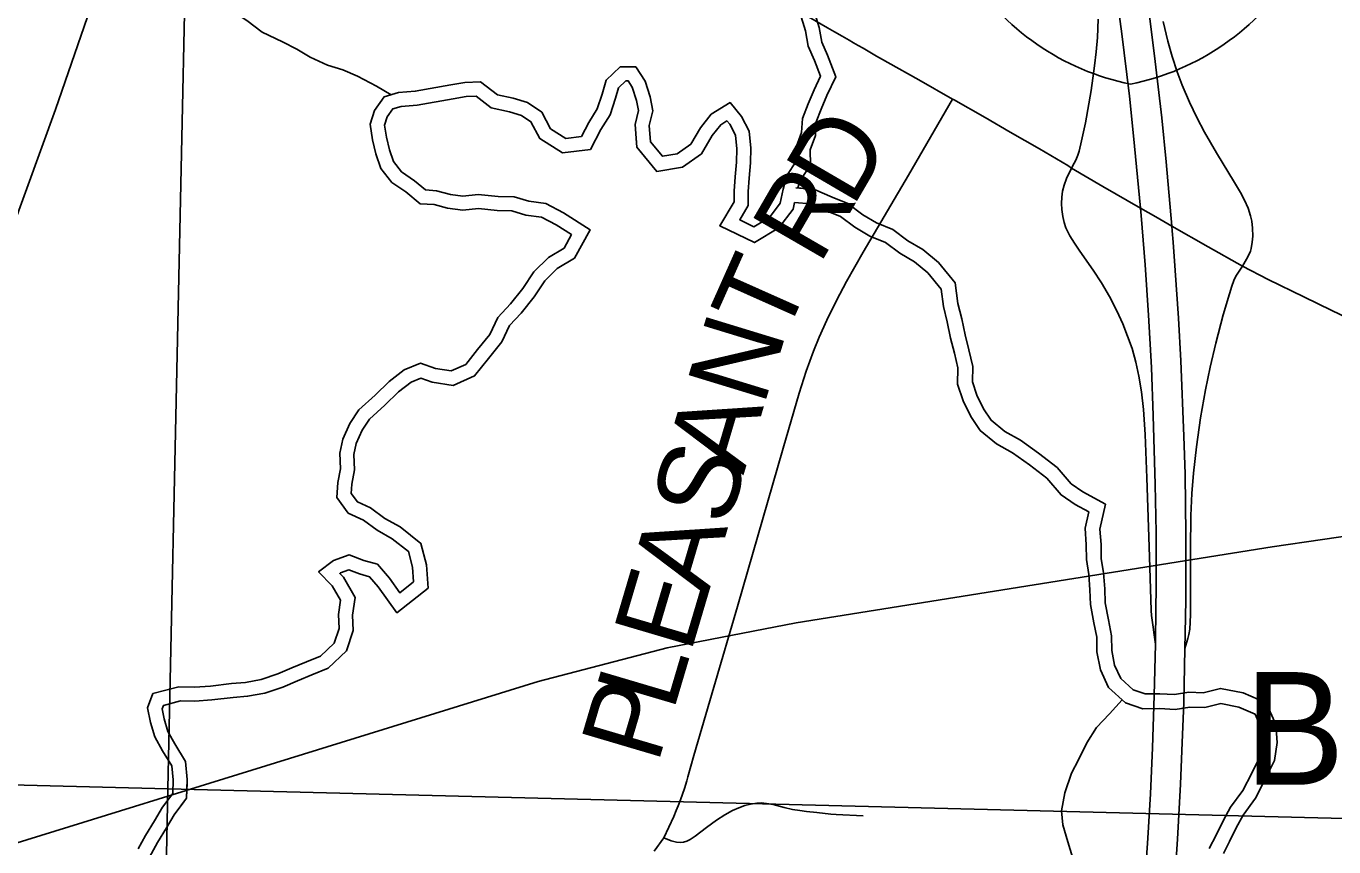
# Model space of a CAD drawing. Extents: x 0 to 34, y 0 to 22.
# Drawn here: x 29.042 to 29.958, y 19.567 to 20.143 of the extents above; entities that cross this region are included whole.
import ezdxf

# ---------------------------------------------------------------- set-up
doc = ezdxf.new("R2010")
doc.units = 0
for name, color, linetype in [('GM_X_Corporation', 7, 'Continuous'), ('GM_X_County_Road', 7, 'Continuous'), ('GM_X_County_Road_Text', 7, 'Continuous'), ('GM_X_Interchange_Ramps', 7, 'Continuous'), ('GM_X_Interstate_Route', 7, 'Continuous'), ('GM_X_Interstate_Shield', 7, 'Continuous'), ('GM_X_Major_River', 7, 'Continuous'), ('GM_X_Minor_River', 7, 'Continuous'), ('GM_X_Rail_Line', 7, 'Continuous'), ('GM_X_State_Route', 7, 'Continuous'), ('GM_X_Township_Road', 7, 'Continuous'), ('GM_X_Unincorporated_Text', 7, 'Continuous')]:
    doc.layers.add(name, color=color, linetype=linetype)

msp = doc.modelspace()

# ---------------------------------------------------------------- linework, layer by layer
at = {"layer": 'GM_X_Corporation'}
for points in [[(28.15826, 20.64503), (29.16312, 20.61871), (29.14139, 19.60821), (28.13428, 19.63375)], [(29.16312, 20.61871), (29.66671, 20.60283), (30.17754, 20.58732), (30.18242, 20.58723), (30.15988, 19.58241), (29.14139, 19.60821)], [(30.15988, 19.58241), (30.13818, 18.56889), (29.12079, 18.59588), (29.14139, 19.60821)]]:
    msp.add_lwpolyline(points, close=True, dxfattribs=at)
at = {"layer": 'GM_X_County_Road'}
for points in [[(29.5056, 19.61665), (29.50985, 19.63157), (29.52386, 19.67928), (29.54025, 19.73585), (29.57229, 19.84674), (29.58363, 19.88549), (29.58855, 19.90085), (29.59364, 19.91483), (29.59758, 19.9246), (29.60286, 19.93649), (29.6097, 19.95041), (29.61667, 19.96357), (29.62828, 19.9841), (29.66011, 20.0382), (29.68838, 20.0869), (29.69105, 20.09149)], [(29.48863, 19.57377), (29.49573, 19.58872), (29.49749, 19.59284), (29.49877, 19.59613), (29.50038, 19.60046), (29.50315, 19.6084), (29.50481, 19.61385), (29.5056, 19.61665)], [(29.48199, 19.56437), (29.48863, 19.57377)]]:
    msp.add_lwpolyline(points, dxfattribs=at)
at = {"layer": 'GM_X_Interchange_Ramps'}
for points in [[(29.79303, 20.14754), (29.79241, 20.13451), (29.79162, 20.12461), (29.79052, 20.11475), (29.78807, 20.09755), (29.78406, 20.07493), (29.78143, 20.06217), (29.77964, 20.05495), (29.77879, 20.05221), (29.7773, 20.04877), (29.77609, 20.04647), (29.77427, 20.04315)], [(29.8942, 19.97448), (29.89792, 19.98093), (29.89965, 19.98491), (29.9002, 19.98683), (29.90094, 19.99111), (29.90127, 19.99544), (29.90116, 20.00104), (29.90056, 20.00596), (29.89981, 20.0096), (29.89814, 20.01494), (29.89559, 20.02059), (29.8927, 20.02607), (29.88858, 20.03302), (29.87598, 20.05371), (29.86756, 20.06821), (29.86206, 20.07864), (29.857, 20.08929), (29.85192, 20.10131), (29.84843, 20.11061), (29.84493, 20.12122), (29.84184, 20.13196), (29.83854, 20.14585)], [(29.77427, 20.04315), (29.77089, 20.03589), (29.76917, 20.03122), (29.76806, 20.02701), (29.76743, 20.02271), (29.76724, 20.01837), (29.76747, 20.01402), (29.76816, 20.00909), (29.76924, 20.00489), (29.77043, 20.00135), (29.7731, 19.99574), (29.77635, 19.99045), (29.78019, 19.9848), (29.78944, 19.97153), (29.79522, 19.96268), (29.80089, 19.95303), (29.80602, 19.94309), (29.81017, 19.93405), (29.81365, 19.9254), (29.81672, 19.91658), (29.81939, 19.907), (29.82156, 19.8973), (29.8234, 19.88626), (29.82473, 19.8739), (29.82583, 19.85652), (29.82707, 19.82608), (29.82891, 19.77077), (29.83002, 19.73301), (29.83042, 19.72952), (29.83073, 19.72636), (29.83145, 19.72133), (29.83221, 19.71605), (29.83313, 19.70959)], [(29.85379, 19.70653), (29.8557, 19.71347), (29.85651, 19.71639), (29.85711, 19.72012), (29.85764, 19.73001), (29.85773, 19.74739), (29.85769, 19.77596), (29.85797, 19.79955), (29.8587, 19.81505), (29.85983, 19.82929), (29.86188, 19.8478), (29.86478, 19.86809), (29.86809, 19.88768), (29.87134, 19.90349), (29.87534, 19.92041), (29.88051, 19.94022), (29.88491, 19.9551), (29.88664, 19.96036), (29.88794, 19.96429), (29.88871, 19.96596), (29.88994, 19.96802), (29.8942, 19.97448)]]:
    msp.add_lwpolyline(points, dxfattribs=at)
at = {"layer": 'GM_X_Interstate_Route'}
for points in [[(29.84542, 19.99124), (29.84478, 19.9992), (29.84449, 20.00246), (29.84059, 20.04748), (29.83748, 20.07838), (29.83297, 20.11788), (29.82873, 20.15177), (29.82454, 20.18192), (29.81814, 20.22429), (29.81289, 20.25616), (29.80444, 20.30387), (29.80109, 20.3216), (29.7974, 20.3411), (29.79259, 20.36484), (29.78366, 20.40612), (29.77461, 20.44548), (29.76021, 20.50592), (29.75342, 20.53433), (29.74589, 20.56638), (29.72925, 20.63524), (29.72152, 20.66788), (29.71159, 20.70896), (29.68623, 20.81534)], [(29.82515, 19.53568), (29.8278, 19.57349), (29.82956, 19.60451), (29.83098, 19.6368), (29.83229, 19.67344), (29.83313, 19.70959), (29.83321, 19.71321), (29.83361, 19.75112), (29.83351, 19.78779), (29.833, 19.82135), (29.83163, 19.86981), (29.83027, 19.90334), (29.82832, 19.93996), (29.82587, 19.97531), (29.823, 20.01), (29.82253, 20.01505), (29.81781, 20.06569), (29.81484, 20.0935), (29.80922, 20.13915), (29.80183, 20.19271)], [(29.84637, 19.54128), (29.84846, 19.57287), (29.85056, 19.61132), (29.85192, 19.64049), (29.85293, 19.66842), (29.85379, 19.70653), (29.85402, 19.71686), (29.85431, 19.74046), (29.8543, 19.78642), (29.85382, 19.82865), (29.85301, 19.85535), (29.85082, 19.9081), (29.84927, 19.93788), (29.84701, 19.97134), (29.84542, 19.99124)]]:
    msp.add_lwpolyline(points, dxfattribs=at)
at = {"layer": 'GM_X_Interstate_Shield'}
for centre, start, end in [((29.85117, 20.27584), 165.80665, 258.46304), ((29.78015, 20.27584), 281.53696, 14.19335)]:
    msp.add_arc(centre, 0.17756, start, end, dxfattribs=at)
at = {"layer": 'GM_X_Major_River'}
for points in [[(29.5827, 20.0292), (29.58395, 20.03384), (29.59144, 20.04532), (29.59134, 20.05601), (29.5949, 20.06591), (29.59556, 20.07561), (29.59904, 20.0844), (29.603, 20.09402), (29.60914, 20.10714), (29.60331, 20.12212), (29.59942, 20.13145), (29.59753, 20.14155), (29.5934, 20.15517)], [(29.58329, 20.0314), (29.58395, 20.03384), (29.59144, 20.04532), (29.59134, 20.05601), (29.5949, 20.06591), (29.59556, 20.07561), (29.59904, 20.0844), (29.603, 20.09402), (29.60914, 20.10714), (29.60331, 20.12212), (29.59942, 20.13145), (29.59753, 20.14155), (29.5934, 20.15517)], [(29.47939, 20.06154), (29.4878, 20.0514), (29.49799, 20.05302), (29.50776, 20.05994), (29.51446, 20.07138), (29.52194, 20.08093), (29.5351, 20.08903), (29.54313, 20.07926), (29.54851, 20.06908), (29.54975, 20.05697), (29.54946, 20.04673), (29.54842, 20.03611), (29.54775, 20.02663), (29.54783, 20.01678), (29.54187, 20.00687), (29.55174, 20.00205), (29.56265, 20.0086), (29.57012, 20.01853), (29.5723, 20.02841), (29.57487, 20.03791), (29.58158, 20.04821), (29.5815, 20.05768), (29.58519, 20.06795), (29.58586, 20.07781), (29.58993, 20.08808), (29.594, 20.09798), (29.59845, 20.1075), (29.59419, 20.11844), (29.58995, 20.12863), (29.58796, 20.13922), (29.58407, 20.15206)], [(29.14468, 19.60487), (29.14497, 19.61435), (29.14413, 19.62419), (29.13761, 19.63473), (29.13223, 19.64452), (29.12912, 19.65472), (29.12714, 19.66493), (29.13084, 19.67482), (29.14894, 19.67956), (29.15991, 19.67929), (29.17124, 19.68017), (29.18597, 19.68184), (29.19579, 19.6827), (29.20673, 19.68471), (29.21842, 19.68862), (29.22821, 19.69289), (29.23838, 19.69716), (29.24817, 19.70106), (29.25792, 19.71025), (29.26123, 19.72052), (29.26077, 19.73036), (29.2622, 19.74023), (29.25644, 19.7504), (29.2469, 19.76015), (29.25741, 19.76822), (29.26834, 19.77212), (29.27859, 19.76806), (29.28806, 19.76551), (29.29646, 19.75574), (29.30373, 19.74559), (29.31349, 19.75327), (29.31265, 19.76349), (29.30991, 19.77445), (29.29849, 19.78342), (29.28785, 19.78937), (29.27834, 19.79648), (29.26771, 19.80129), (29.25968, 19.81219), (29.26034, 19.82281), (29.26215, 19.8323), (29.26167, 19.84328), (29.26385, 19.85316), (29.26867, 19.8642), (29.27502, 19.87374), (29.28664, 19.88409), (29.29639, 19.89366), (29.3069, 19.90173), (29.3182, 19.90639), (29.32882, 19.90272), (29.3398, 19.90094), (29.34996, 19.90559), (29.35819, 19.91591), (29.36679, 19.92661), (29.37236, 19.93841), (29.38135, 19.94798), (29.38995, 19.95868), (29.39778, 19.9705), (29.4079, 19.98046), (29.41881, 19.98702), (29.42402, 19.99655), (29.41337, 20.00325), (29.40312, 20.00883), (29.39214, 20.01023), (29.38229, 20.01316), (29.37208, 20.01343), (29.35884, 20.01481), (29.34788, 20.01356), (29.33729, 20.01496), (29.32781, 20.01752), (29.31798, 20.01817), (29.30808, 20.02641), (29.29819, 20.03312), (29.29054, 20.0429), (29.28705, 20.05309), (29.2847, 20.06292), (29.28309, 20.07389), (29.28603, 20.08339), (29.29275, 20.09294), (29.30293, 20.09607), (29.31464, 20.09696), (29.33955, 20.10138), (29.34937, 20.103), (29.36033, 20.1035), (29.37212, 20.09452), (29.38311, 20.09199), (29.39334, 20.08906), (29.40323, 20.08234), (29.40938, 20.07066), (29.42002, 20.06395), (29.43098, 20.0652), (29.43618, 20.07511), (29.44214, 20.08465), (29.44546, 20.09491), (29.44839, 20.10479), (29.45814, 20.11399), (29.4691, 20.1141), (29.47562, 20.10394), (29.47912, 20.09299), (29.48109, 20.08316), (29.47854, 20.0729), (29.47939, 20.06154)], [(29.15451, 19.60456), (29.15482, 19.61461), (29.15373, 19.62737), (29.14611, 19.63968), (29.14134, 19.64837), (29.13867, 19.6571), (29.13732, 19.66409), (29.13826, 19.6666), (29.15009, 19.6697), (29.16016, 19.66945), (29.17217, 19.67038), (29.18695, 19.67206), (29.19711, 19.67295), (29.20919, 19.67516), (29.22195, 19.67944), (29.23208, 19.68385), (29.2421, 19.68806), (29.25355, 19.69262), (29.2665, 19.70483), (29.27114, 19.71919), (29.27063, 19.72989), (29.27241, 19.74215), (29.26436, 19.75636), (29.26168, 19.7591), (29.26218, 19.75948), (29.26816, 19.76162), (29.27548, 19.75871), (29.28258, 19.7568), (29.28872, 19.74966), (29.30173, 19.7315), (29.32373, 19.74881), (29.32238, 19.7651), (29.31862, 19.7801), (29.30396, 19.79163), (29.29321, 19.79764), (29.28336, 19.80499), (29.2741, 19.80919), (29.26971, 19.81515), (29.27011, 19.82158), (29.27202, 19.83159), (29.27155, 19.84242), (29.27325, 19.8501), (29.27734, 19.85947), (29.2825, 19.86724), (29.29336, 19.87691), (29.30285, 19.88623), (29.31186, 19.89314), (29.31851, 19.89588), (29.32641, 19.89315), (29.34117, 19.89075), (29.35619, 19.89763), (29.36586, 19.90976), (29.37518, 19.92135), (29.38059, 19.93281), (29.38877, 19.94152), (29.39789, 19.95287), (29.40541, 19.96422), (29.41397, 19.97264), (29.42616, 19.97996), (29.43708, 19.99993), (29.41835, 20.01174), (29.40619, 20.01835), (29.39418, 20.01988), (29.38384, 20.02295), (29.37272, 20.02325), (29.35878, 20.0247), (29.34797, 20.02346), (29.33922, 20.02462), (29.32943, 20.02726), (29.32181, 20.02777), (29.31399, 20.03427), (29.30498, 20.04039), (29.29931, 20.04765), (29.2965, 20.05583), (29.29436, 20.06478), (29.29314, 20.07311), (29.29496, 20.079), (29.29885, 20.08453), (29.30477, 20.08635), (29.31587, 20.08719), (29.34121, 20.09169), (29.35039, 20.09321), (29.35721, 20.09351), (29.36785, 20.08542), (29.38065, 20.08246), (29.38912, 20.08004), (29.39567, 20.07559), (29.40191, 20.06375), (29.4177, 20.05379), (29.43726, 20.05602), (29.44471, 20.07021), (29.45113, 20.08046), (29.45485, 20.092), (29.45706, 20.09945), (29.46209, 20.1042), (29.46377, 20.10422), (29.46665, 20.09972), (29.46959, 20.09051), (29.47102, 20.08339), (29.46862, 20.07374), (29.46959, 20.0608)], [(29.15441, 19.60148), (29.15482, 19.61461), (29.15373, 19.62737), (29.14611, 19.63968), (29.14134, 19.64837), (29.13867, 19.6571), (29.13732, 19.66409), (29.13826, 19.6666), (29.15009, 19.6697), (29.16016, 19.66945), (29.17217, 19.67038), (29.18695, 19.67206), (29.19711, 19.67295), (29.20919, 19.67516), (29.22195, 19.67944), (29.23208, 19.68385), (29.2421, 19.68806), (29.25355, 19.69262), (29.2665, 19.70483), (29.27114, 19.71919), (29.27063, 19.72989), (29.27241, 19.74215), (29.26436, 19.75636), (29.26168, 19.7591), (29.26218, 19.75948), (29.26816, 19.76162), (29.27548, 19.75871), (29.28258, 19.7568), (29.28872, 19.74966), (29.30173, 19.7315), (29.32373, 19.74881), (29.32238, 19.7651), (29.31862, 19.7801), (29.30396, 19.79163), (29.29321, 19.79764), (29.28336, 19.80499), (29.2741, 19.80919), (29.26971, 19.81515), (29.27011, 19.82158), (29.27202, 19.83159), (29.27155, 19.84242), (29.27325, 19.8501), (29.27734, 19.85947), (29.2825, 19.86724), (29.29336, 19.87691), (29.30285, 19.88623), (29.31186, 19.89314), (29.31851, 19.89588), (29.32641, 19.89315), (29.34117, 19.89075), (29.35619, 19.89763), (29.36586, 19.90976), (29.37518, 19.92135), (29.38059, 19.93281), (29.38877, 19.94152), (29.39789, 19.95287), (29.40541, 19.96422), (29.41397, 19.97264), (29.42616, 19.97996), (29.43708, 19.99993), (29.41835, 20.01174), (29.40619, 20.01835), (29.39418, 20.01988), (29.38384, 20.02295), (29.37272, 20.02325), (29.35878, 20.0247), (29.34797, 20.02346), (29.33922, 20.02462), (29.32943, 20.02726), (29.32181, 20.02777), (29.31399, 20.03427), (29.30498, 20.04039), (29.29931, 20.04765), (29.2965, 20.05583), (29.29436, 20.06478), (29.29314, 20.07311), (29.29496, 20.079), (29.29885, 20.08453), (29.30477, 20.08635), (29.31587, 20.08719), (29.34121, 20.09169), (29.35039, 20.09321), (29.35721, 20.09351), (29.36785, 20.08542), (29.38065, 20.08246), (29.38912, 20.08004), (29.39567, 20.07559), (29.40191, 20.06375), (29.4177, 20.05379), (29.43726, 20.05602), (29.44471, 20.07021), (29.45113, 20.08046), (29.45485, 20.092), (29.45706, 20.09945), (29.46209, 20.1042), (29.46377, 20.10422), (29.46665, 20.09972), (29.46959, 20.09051), (29.47102, 20.08339), (29.46862, 20.07374), (29.46983, 20.05768)], [(29.46983, 20.05768), (29.48381, 20.04081), (29.5018, 20.04367), (29.51517, 20.05314), (29.52261, 20.06584), (29.52859, 20.07348), (29.53295, 20.07616), (29.5349, 20.07379), (29.53892, 20.06618), (29.5399, 20.05661), (29.53964, 20.04736), (29.53862, 20.03694), (29.53791, 20.02694), (29.53798, 20.01947), (29.52792, 20.00275), (29.55223, 19.99087), (29.56935, 20.00116), (29.57926, 20.01433), (29.58029, 20.019)], [(29.47182, 20.05527), (29.48381, 20.04081), (29.5018, 20.04367), (29.51517, 20.05314), (29.52261, 20.06584), (29.52859, 20.07348), (29.53295, 20.07616), (29.5349, 20.07379), (29.53892, 20.06618), (29.5399, 20.05661), (29.53964, 20.04736), (29.53862, 20.03694), (29.53791, 20.02694), (29.53798, 20.01947), (29.52792, 20.00275), (29.55223, 19.99087), (29.56935, 20.00116), (29.57926, 20.01433), (29.58029, 20.019)], [(29.5812, 20.02933), (29.59427, 20.02819), (29.60673, 20.02274), (29.61773, 20.0182), (29.62823, 20.01027), (29.6377, 20.00464), (29.64923, 19.99999), (29.65972, 19.99207), (29.67018, 19.986), (29.68115, 19.97694), (29.69282, 19.9626), (29.69475, 19.94817), (29.6974, 19.93758), (29.69976, 19.92627), (29.70247, 19.9158), (29.70515, 19.90419), (29.70488, 19.89331), (29.70797, 19.884), (29.71275, 19.87431), (29.71803, 19.86638), (29.72752, 19.8586), (29.73866, 19.85242), (29.75108, 19.84338), (29.76423, 19.83329), (29.77396, 19.82188), (29.78228, 19.81622), (29.79818, 19.80751), (29.79427, 19.79), (29.79504, 19.77945), (29.79512, 19.76963), (29.79667, 19.7594), (29.79757, 19.74826), (29.79801, 19.73857), (29.80025, 19.72646), (29.80241, 19.71536), (29.80249, 19.70511), (29.80445, 19.69481), (29.80882, 19.68541), (29.81748, 19.67744), (29.82586, 19.67465), (29.8362, 19.67476), (29.8464, 19.67416), (29.85642, 19.67576), (29.86657, 19.6755), (29.87879, 19.67849), (29.89458, 19.67531), (29.91076, 19.66847), (29.91733, 19.6533), (29.91841, 19.64059), (29.91658, 19.62787), (29.90984, 19.6145), (29.90314, 19.60156), (29.89448, 19.58963), (29.8897, 19.5809), (29.88495, 19.57114), (29.88071, 19.56279)], [(29.88071, 19.56279), (29.88495, 19.57114), (29.8897, 19.5809), (29.89448, 19.58963), (29.90314, 19.60156), (29.90984, 19.6145), (29.91658, 19.62787), (29.91841, 19.64059), (29.91733, 19.6533), (29.91076, 19.66847), (29.89458, 19.67531), (29.87879, 19.67849), (29.86657, 19.6755), (29.85642, 19.67576), (29.8464, 19.67416), (29.8362, 19.67476), (29.82586, 19.67465), (29.81748, 19.67744), (29.80882, 19.68541), (29.80445, 19.69481), (29.80249, 19.70511), (29.80241, 19.71536), (29.80025, 19.72646), (29.79801, 19.73857), (29.79757, 19.74826), (29.79667, 19.7594), (29.79512, 19.76963), (29.79504, 19.77945), (29.79427, 19.79), (29.79818, 19.80751), (29.78228, 19.81622), (29.77396, 19.82188), (29.76423, 19.83329), (29.75108, 19.84338), (29.73866, 19.85242), (29.72752, 19.8586), (29.71803, 19.86638), (29.71275, 19.87431), (29.70797, 19.884), (29.70488, 19.89331), (29.70515, 19.90419), (29.70247, 19.9158), (29.69976, 19.92627), (29.6974, 19.93758), (29.69475, 19.94817), (29.69282, 19.9626), (29.68115, 19.97694), (29.67018, 19.986), (29.65972, 19.99207), (29.64923, 19.99999), (29.6377, 20.00464), (29.62823, 20.01027), (29.61773, 20.0182), (29.60673, 20.02274), (29.59427, 20.02819), (29.5827, 20.0292)], [(29.58029, 20.019), (29.59167, 20.018), (29.60268, 20.01319), (29.61254, 20.00912), (29.62244, 20.00165), (29.63308, 19.99532), (29.64408, 19.99088), (29.65397, 19.98341), (29.66423, 19.97745), (29.67375, 19.9696), (29.68292, 19.95833), (29.68454, 19.94622), (29.68728, 19.93526), (29.68965, 19.92391), (29.69239, 19.91333), (29.69475, 19.90313), (29.69447, 19.89176), (29.69835, 19.88005), (29.70374, 19.86912), (29.71025, 19.85934), (29.72167, 19.84998), (29.73307, 19.84366), (29.74487, 19.83507), (29.75704, 19.82573), (29.76697, 19.81408), (29.77686, 19.80737), (29.78636, 19.80216), (29.78381, 19.79077), (29.78467, 19.77903), (29.78476, 19.7688), (29.78636, 19.75821), (29.78721, 19.74761), (29.78768, 19.73738), (29.79006, 19.72453), (29.79204, 19.71432), (29.79213, 19.70409), (29.79451, 19.69161), (29.80028, 19.67917), (29.8121, 19.6683), (29.82423, 19.66426), (29.83595, 19.66438), (29.84692, 19.66374), (29.85711, 19.66536), (29.8677, 19.66509), (29.87901, 19.66787), (29.89151, 19.66534), (29.90289, 19.66054), (29.90714, 19.65073), (29.90798, 19.64089), (29.90655, 19.63102), (29.90061, 19.61922), (29.89429, 19.60703), (29.8857, 19.59519), (29.88048, 19.58566), (29.87566, 19.57576), (29.87083, 19.56624)], [(29.12045, 19.56597), (29.12565, 19.5755), (29.13199, 19.5858), (29.13758, 19.59532), (29.14468, 19.60487)], [(29.12856, 19.56032), (29.13416, 19.57056), (29.14042, 19.58073), (29.14579, 19.58989), (29.15441, 19.60148)], [(29.12856, 19.56032), (29.13416, 19.57056), (29.14042, 19.58073), (29.14579, 19.58989), (29.15257, 19.59901)]]:
    msp.add_lwpolyline(points, dxfattribs=at)
at = {"layer": 'GM_X_Minor_River'}
for points in [[(29.29784, 20.09451), (29.28739, 20.10046), (29.2741, 20.10752), (29.26385, 20.11196), (29.25324, 20.11526), (29.24109, 20.12082), (29.23159, 20.1264), (29.22172, 20.13161), (29.20729, 20.13827), (29.19664, 20.1465), (29.18485, 20.15434), (29.1723, 20.1633), (29.16014, 20.16999), (29.15026, 20.17595), (29.13811, 20.18151), (29.12825, 20.18557), (29.11194, 20.19185), (29.09828, 20.19701), (29.0869, 20.20182), (29.07174, 20.20621), (29.06186, 20.21141), (29.05046, 20.21811), (29.03491, 20.22477)], [(29.80973, 19.67048), (29.80082, 19.66061), (29.79184, 19.65104), (29.78512, 19.64036), (29.77918, 19.62855), (29.77435, 19.61903), (29.76955, 19.60534), (29.76739, 19.59282), (29.76824, 19.58298), (29.77174, 19.57089), (29.77602, 19.55729)]]:
    msp.add_lwpolyline(points, dxfattribs=at)
at = {"layer": 'GM_X_Rail_Line'}
for points in [[(28.87412, 19.5654), (29.06268, 20.08407), (29.08941, 20.1621), (29.11423, 20.24091), (29.13556, 20.33631), (29.14735, 20.40617), (29.15508, 20.46387), (29.16098, 20.49637)], [(28.85149, 19.51339), (29.40069, 19.68335), (29.49101, 19.70696), (29.58134, 19.72441), (29.91492, 19.77777), (30.02064, 19.79316), (30.11506, 19.80445), (30.18589, 19.8065), (30.24747, 19.80957), (30.28674, 19.81703), (30.31667, 19.82835)]]:
    msp.add_lwpolyline(points, dxfattribs=at)
at = {"layer": 'GM_X_State_Route'}
for points in [[(29.59008, 20.14919), (29.6035, 20.14145), (29.6083, 20.13862), (29.61362, 20.13548), (29.61845, 20.13272), (29.62167, 20.13089), (29.62486, 20.129), (29.62828, 20.12703)], [(29.62828, 20.12703), (29.63769, 20.12163), (29.64198, 20.11919), (29.64574, 20.11706), (29.66731, 20.10492), (29.69105, 20.09149), (29.6916, 20.09118), (29.71373, 20.07861), (29.73146, 20.06832), (29.75189, 20.05649), (29.7717, 20.04484), (29.77427, 20.04315), (29.79622, 20.0302), (29.82253, 20.01505), (29.83334, 20.00884), (29.84449, 20.00246), (29.86998, 19.98789), (29.8942, 19.97448), (29.91202, 19.96502), (29.93702, 19.9528)], [(29.93702, 19.9528), (29.95666, 19.9432), (29.98693, 19.92874), (30.00983, 19.91791), (30.01874, 19.9135)]]:
    msp.add_lwpolyline(points, dxfattribs=at)
at = {"layer": 'GM_X_Township_Road'}
msp.add_lwpolyline([(29.48863, 19.57377), (29.49378, 19.57172), (29.49764, 19.57073), (29.50012, 19.57051), (29.50257, 19.57076), (29.50488, 19.57153), (29.50709, 19.57263), (29.5107, 19.57505), (29.51861, 19.58113), (29.52567, 19.5862), (29.5314, 19.58989), (29.53681, 19.59288), (29.54131, 19.59492), (29.54537, 19.59638), (29.54955, 19.59746), (29.55382, 19.59805), (29.55704, 19.5984), (29.56057, 19.59794), (29.56543, 19.59708), (29.57301, 19.59511), (29.57889, 19.59366), (29.58404, 19.59284), (29.58877, 19.59224), (29.5958, 19.59156), (29.60567, 19.59046), (29.60938, 19.59009), (29.62835, 19.58914)], dxfattribs=at)

# ---------------------------------------------------------------- texts
at = {"layer": 'GM_X_County_Road_Text'}
for s, rotation, p in [('D', 59.71471, (29.62095, 20.01468)), ('R', 59.9419, (29.5976, 19.97434)), ('T', 65.97137, (29.57263, 19.92157)), ('N', 73.00225, (29.55866, 19.87548)), ('A', 73.50068, (29.54449, 19.82766)), ('S', 73.5044, (29.53361, 19.7909)), ('A', 73.50818, (29.51942, 19.74296)), ('E', 73.50602, (29.50735, 19.70221)), ('L', 73.50472, (29.49528, 19.66146)), ('P', 73.5044, (29.4844, 19.6247))]:
    msp.add_text(s, height=0.05682, rotation=rotation, dxfattribs=at).set_placement(p)
at = {"layer": 'GM_X_Unincorporated_Text'}
msp.add_text('Buffalo', height=0.078977, rotation=0.00001, dxfattribs=at).set_placement((29.89528, 19.61096))

doc.saveas('drawing.dxf')
